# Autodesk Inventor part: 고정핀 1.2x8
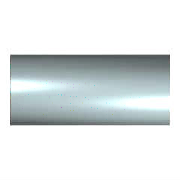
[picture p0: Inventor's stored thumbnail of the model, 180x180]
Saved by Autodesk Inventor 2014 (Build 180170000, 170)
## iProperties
IsCustomPart: 1
Created: 2012-02
Part Number: 고정핀 1.2x8
Material: 강철, 연강
Description: 평행 핀
Document SubType Name: Modeling
Standard: KS B 1320
Designer: P15F
Standards Organization: KS
Language: ko-KR
Size Designation: C 1.2 x  8
Categories: <MemberInstance><Categories><Category DisplayName="조임쇠" InternalName="e4da775c-781d-43d5-af7c-5136215cf5a6" Mnemonic="FSTN"><Category DisplayName="핀" InternalNa
Density: 1 g/cm^3
Appearance: 노란색
Author: P15F
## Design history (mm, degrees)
sketch "스케치1"
  geometry: C1 r 0.6 at (0, 0); 1 further point
  constraints: 1 centre point, 1 coincident
  dimensions: "d1" = 1.2 diameter of C1 (= NND)
extrude "본체" new body sketch "스케치1" distance "d2" = 8 (= NLG); taper "d3" = 0 deg
node "작업 평면1"
node "작업 평면2"
body "Solid1"
other parameters: "NND" = 1.2 [user parameter; used in 1 equation term], "NLG" = 8 [user parameter; used in 1 equation term], "d8" = 0, "d9" = 0, "d10" = 0
